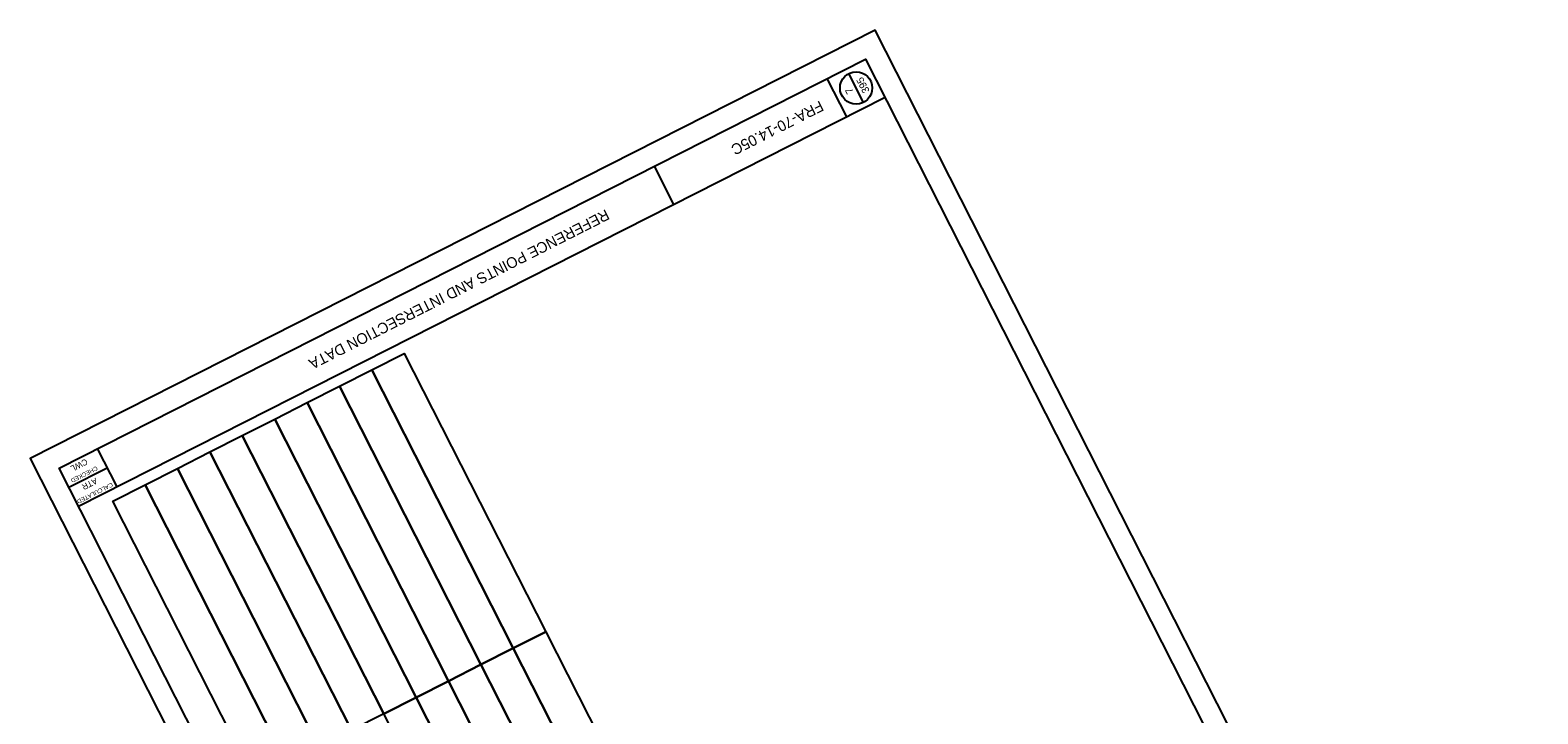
# Model space of a CAD drawing. Extents: x 1823249 to 1826750, y 706322 to 710350.
# Drawn here: x 1823249 to 1826750, y 708761 to 710350 of the extents above; entities that cross this region are included whole.
import ezdxf

# ---------------------------------------------------------------- set-up
doc = ezdxf.new("R2010")
doc.units = 0
for name, color, linetype in [('SH_Border', 7, 'Continuous'), ('SH_Cut_Line', 7, 'Continuous'), ('SH_Data', 7, 'Continuous'), ('TX_P_Misc', 7, 'Continuous')]:
    doc.layers.add(name, color=color, linetype=linetype)

msp = doc.modelspace()

# ---------------------------------------------------------------- linework, layer by layer
at = {"layer": 'SH_Border'}
for p, q in [((1825145.3, 710148.4), (1825100, 710237.6)), ((1825234.5, 710193.6), (1823361.9, 709243.1)), ((1824744, 709944.7), (1824698.8, 710033.9)), ((1823451.1, 709288.4), (1823405.8, 709377.6)), ((1823339.3, 709287.7), (1823428.5, 709333))]:
    msp.add_line(p, q, dxfattribs=at)
msp.add_lwpolyline([(1824742.4, 706523.4), (1823316.6, 709332.3), (1825189.2, 710282.8), (1826615, 707474)], close=True, dxfattribs=at)
at = {"layer": 'SH_Cut_Line'}
msp.add_lwpolyline([(1826750.1, 707318.3), (1825211.2, 710350), (1823249.4, 709354.2), (1824788.4, 706322.5)], close=True, dxfattribs=at)
at = {"layer": 'SH_Data'}
msp.add_line((1825184.2, 710182.2), (1825150.3, 710249), dxfattribs=at)
msp.add_circle((1825167.3, 710215.6), 37.5, dxfattribs=at)
at = {"layer": 'TX_P_Misc'}
for points in [[(1824371.3, 708913.8), (1824043, 709560.7), (1824118.2, 709598.9), (1824446.6, 708952)], [(1824296.1, 708875.6), (1823967.7, 709522.5), (1824043, 709560.7), (1824371.3, 708913.8)], [(1824220.9, 708837.4), (1823892.5, 709484.3), (1823967.7, 709522.5), (1824296.1, 708875.6)], [(1824145.7, 708799.2), (1823817.3, 709446.1), (1823892.5, 709484.3), (1824220.9, 708837.4)], [(1824070.4, 708761), (1823742, 709407.9), (1823817.3, 709446.1), (1824145.7, 708799.2)], [(1823995.2, 708722.8), (1823666.8, 709369.7), (1823742, 709407.9), (1824070.4, 708761)], [(1823920, 708684.6), (1823591.6, 709331.6), (1823666.8, 709369.7), (1823995.2, 708722.8)], [(1823844.7, 708646.5), (1823516.4, 709293.4), (1823591.6, 709331.6), (1823920, 708684.6)], [(1824097.9, 707961.4), (1823441.1, 709255.2), (1823516.4, 709293.4), (1824173.1, 707999.6)], [(1824699.7, 708266.9), (1824371.3, 708913.8), (1824446.6, 708952), (1824775, 708305.1)], [(1824624.5, 708228.7), (1824296.1, 708875.6), (1824371.3, 708913.8), (1824699.7, 708266.9)], [(1824549.3, 708190.5), (1824220.9, 708837.4), (1824296.1, 708875.6), (1824624.5, 708228.7)], [(1824474, 708152.3), (1824145.7, 708799.2), (1824220.9, 708837.4), (1824549.3, 708190.5)], [(1824398.8, 708114.1), (1824070.4, 708761), (1824145.7, 708799.2), (1824474, 708152.3)]]:
    msp.add_lwpolyline(points, close=True, dxfattribs=at)

# ---------------------------------------------------------------- texts
at = {"layer": 'SH_Data'}
for s, height, rotation, p in [('395', 17, 116.9125, (1825199.1, 710208.8)), (' FRA-70-14.05C  ', 25, 206.9125, (1825091.5, 710191.1)), ('7', 17, 116.9125, (1825161.8, 710206.8)), ('   REFERENCE POINTS AND INTERSECTION DATA   ', 25, 206.9125, (1824610.8, 709947.1)), ('CWL', 14, 206.9125, (1823378.5, 709354.7)), ('CHECKED', 10, 206.9125, (1823403, 709337.2)), ('ATR', 14, 206.9125, (1823401.1, 709310.1)), ('CALCULATED', 10, 206.9125, (1823438.4, 709299.1))]:
    msp.add_text(s, height=height, rotation=rotation, dxfattribs=at).set_placement(p)

doc.saveas('drawing.dxf')
